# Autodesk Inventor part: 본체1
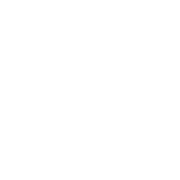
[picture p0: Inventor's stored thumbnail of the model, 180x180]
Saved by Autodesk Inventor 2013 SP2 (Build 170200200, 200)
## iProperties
Created: 2024-08
Part Number: 본체1
Material: Generic
Document SubType Name: Modeling
Designer: a
Density: 1 g/cm^3
Author: a
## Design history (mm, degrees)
sketch "스케치1"
  geometry: C1 r 71 at (0, 0); 1 further point
  constraints: 1 centre point, 1 coincident
  dimensions: "d0" = 142 diameter of C1
extrude "돌출1" new body sketch "스케치1" distance "d2" = 15; taper "d3" = 0 deg
fillet "모깎기2" dims "d5" = 6
sketch "스케치2"
  geometry: L1 (-20, 40.5)-(20, 40.5); L2 (20, 40.5)-(20, -40.5); L3 (20, -40.5)-(-20, -40.5); L4 (-20, -40.5)-(-20, 40.5); L5 (-20, 40.5)-(20, -40.5); L6 (20, 40.5)-(-20, -40.5); C1 r 65 at (0, 0) reference
  constraints: 12 end point, 2 midpoint, 2 parallel, 1 horizontal, 1 perpendicular
  dimensions: "d6" = 40 distance of L1.start L1.end; "d8" = 81 distance of L1.end L2.end
extrude "돌출2" join sketch "스케치2" distance "d9" = 10; taper "d10" = 0 deg
sketch "스케치3"
  geometry: C1 r 11 at (0, 0); 1 further point
  constraints: 1 centre point, 1 coincident
  dimensions: "d11" = 22 diameter of C1
extrude "돌출3" cut sketch "스케치3" distance "d14" = 200; taper "d15" = 0 deg
sketch "스케치4"
  geometry: L1 (20, 40.5)-(20, -40.5) reference; L2 (-20, -40.5)-(-20, 40.5) reference; 4 further points
  dimensions: "d17" = 50 distance of point (30, -17.91) point (30, 32.09); "d19" = 10 distance from line of L2 point (-30, 32.09); "d20" = 50 distance of point (-30, 32.09) point (-30, -17.91); "d21" = 10 horizontal distance of L2.start point (-30, -17.91); "d22" = 10 distance from line of L1 point (30, 32.09); "d23" = 10 horizontal distance of L1.end point (30, -17.91)
hole "구멍1" sketch "스케치4" at (-30, 32.09), (-30, -17.91), (30, 32.09), (30, -17.91) diameter "d24" = 3.242; stored, may be unused: countersink angle "d28" = 82 deg, drill point angle "d30" = 118 deg; dims "d25" = 8, "d26" = 3.023, "d27" = 2, "d29" = 10
node "솔리드1"
